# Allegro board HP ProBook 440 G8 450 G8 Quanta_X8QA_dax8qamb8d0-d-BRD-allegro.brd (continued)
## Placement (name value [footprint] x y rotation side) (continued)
C7735  0.1U/25V_4  [C0402]  136.75 18.39 270 top
C7736  3p/50V_2  [C0201]  121 68.5 0 top
C7737  0.1U/16V_4  [C0402]  95.45 79.86 225 top
C7738  12P/50V_4  [C0402]  110.36 101.72 270 top
C7739  100P/50V_4  [C0402]  111.33 101.72 90 top
C7740  2.2u/25V_4  [C0402_2]  113.03 102.84 270 top
C7741  0.1U/16V_4  [C0402]  114.12 102.84 90 top
C7742  2.2p/50V_4  [C0402]  109.4 101.72 90 top
C7743  2.2p/50V_4  [C0402]  124.48 96.47 270 top
C7744  12P/50V_4  [C0402]  118.74 99.24 0 top
C7745  100P/50V_4  [C0402]  127.07 100.94 90 top
C7746  2.2u/25V_4  [C0402_2]  125.98 100.94 270 top
C7747  0.1U/16V_4  [C0402]  89.05 78.41 225 top
C7748  100P/50V_4  [C0402]  36.4 52.6 0 top
C7749  2.2u/25V_4  [C0402_2]  34.92 54.81 225 top
C7750  0.1U/25V_4  [C0402]  35.68 54.05 45 top
C7751  0.1U/25V_4  [C0402]  64.03 14.7 90 bottom
C7752  0.1U/25V_4  [C0402]  107.06 111.86 180 top
C7753  68P/50V_4  [C0402]  107.06 110.89 180 top
C7754  0.1U/25V_4  [C0402]  153.57 102.66 225 top
C7755  68P/50V_4  [C0402]  155.65 100.73 225 top
C7756  0.1U/25V_4  [C0402]  179.37 89.71 0 top
C7757  2.2p/50V_4  [C0402]  106.95 71.61 270 top
C7758  0.1U/25V_4  [C0402]  111.58 72.41 270 top
C7759  100P/50V_4  [C0402]  107.93 71.61 270 top
C7760  3p/50V_2  [C0201]  134.64 81.46 180 top
C7761  100P/50V_4  [C0402]  129.23 77.82 180 top
C7762  3p/50V_2  [C0201]  113.74 89.86 315 top
C7763  3p/50V_2  [C0201]  129.51 100.99 270 bottom
C7764  100P/50V_4  [C0402]  130.38 100.73 90 bottom
C7765  2.2u/25V_4  [C0402_2]  36.24 27.35 0 top
C7766  0.1U/25V_4  [C0402]  39.9 27.68 0 top
C7767  2.2u/25V_4  [C0402_2]  112.44 96.75 180 bottom
C7768  2.2u/25V_4  [C0402_2]  152.73 19.43 180 top
CON1900  Current monitor conn.  [WTB-50450-0107C-001-10P-L-SMT]  151.33 107.01 0 bottom
CON3400  GS12401-1011-9H  [51693-0400T-V01-40P-L]  22.69 35.5 90 bottom
CON3401  *50376-00601-V01  [50376-00601-V01-6P-L]  8.61 27.76 90 bottom
CON3501  PDMR004019P1-1  [HDMI-PDMR004019P1-1-19P]  214 52.3 270 bottom
CON3601  51378-0040N-V01  [WTB-51378-0040N-V01-4P-L]  138.84 105.6 0 bottom
CON3700  2SJ3095-239251F  [AUDIO-2SJ3095-239251F-6P]  213.52 35.31 270 bottom
CON4100  LOTES_APCI0019-P00*A  [NGFF-NFSE0-S6710-TPH4-KE-SMT]  181.84 77.09 0 bottom
CON4202  NFSB0-S6710-TP20  [NGFF-NFSB0-S6710-TP20-KB-SMT]  193.16 3.74 180 bottom
CON4203  51273-00401-V01  [51273-00401-V01-4P-L]  196.44 48.45 0 bottom
CON4204  5-501709002000-6  [SIMCARD-5-501709002000-6-6P]  167.55 63.46 270 bottom
CON4300  SSD_NGFF_CONN_75P  [NGFF-NFSM0-S6710-TPH4-75P-KM]  8.09 11.5 90 bottom
CON4400  52509-00801-V01  [FPC-52509-00801-V01-8P-L]  28.84 3.75 180 bottom
CON4402  51536-01541-001  [51536-01541-V01-15P-L]  148.49 6.4 180 bottom
CON4700  50271-00201-001  [50271-00201-001-2P-L]  174.34 4.4 180 bottom
CON5000  51697-0420M-001  [FPC-51697-0420M-001-42P-L]  121.39 5.83 180 bottom
CON5002  51614-00801-V01  [51614-00801-V01-8P-L]  46.84 3.35 180 bottom
CON5200  52509-00801-V01  [FPC-52509-00801-V01-8P-L]  158.04 5.6 180 bottom
CON5202  52509-00801-V01  [FPC-52509-00801-V01-8P-L]  37.94 3.77 180 bottom
CON5400  51378-0040N-V01  [WTB-51378-0040N-V01-4P-L]  25.2 63.43 152.7 bottom
CON6201  TCRB5-9U6391  [UB3-TCRB5-9U6391-9P]  213.12 91.9 270 bottom
CON6202  TCRB5-9U6391  [UB3-TCRB5-9U6391-9P]  213.12 72.4 270 bottom
CON6300  UT12123-1090H-7H  [UB31-UT12123-1090H-7H-24P]  214.56 108.72 90 top
CON7600  158-1000902638  [SDCARD-158-1000902616-9P]  213.79 19.4 90 top
CON7602  52526-04001-001  [FPC-52526-04001-001-40P-L]  7.32 16.93 270 top
CON7603  52509-00601-V01  [FPC-52509-00601-V01-6P-L]  0.72 12.3 90 bottom
CON7700  *APS CONN.  [88511-180N-18P-L]  14.3 38.94 90 bottom
CON7701  TBT Debug conn.  [FPC-50506-0150B-V01-15P-L]  163.93 79.58 90 bottom
CON7702  EC debug conn.  [LVDS-50406-03001-V09-30P-R]  212.93 17.47 270 bottom
CON7703  *Samtec BSH-030-01  [BSH-030-01-L-D-A-TR-60P-RUV]  44.5 46.73 270 top
CON7704  52509-00801-V01  [FPC-52509-00801-V01-8P-L]  138.87 5.92 180 bottom
D1400  BAT54CW  [SOT23-1_7-65-3P]  159.05 69.82 90 top
D1500  RB500V-40  [D-1_85X1_25-2P-0_95H]  156.16 78.81 270 bottom
D1600  RB500V-40  [D-1_85X1_25-2P-0_95H]  152.35 67.03 90 bottom
D3300  *RB500V-40  [D-1_85X1_25-2P-0_95H]  19.91 44.12 90 top
D3500  BAT54AW-L  [SOT23-1_7-65-3P]  200.9 48.42 90 top
D3600  *MEK500V-40  [D-1_85X1_25-2P-0_95H]  187.4 45.9 90 top
D3700  Clamp-Diode  [C0402]  204.49 42.75 90 top
D3701  Clamp-Diode  [C0402]  201.8 31.82 90 top
D3702  Clamp-Diode  [C0402]  212.79 28.7 180 bottom
D3703  Clamp-Diode  [C0402]  204.77 42.74 270 bottom
D4200  RB500V-40  [D-1_85X1_25-2P-0_95H]  207.11 10.61 0 bottom
D4201  MEK500V-40  [D-1_85X1_25-2P-0_95H]  205.28 9.42 0 top
D4203  *Clamp-Diode  [C0402]  214.75 10.64 90 top
D4204  *Clamp-Diode  [C0402]  206.27 5.33 0 top
D4205  *Clamp-Diode  [C0402]  197.33 4.01 180 top
D4206  *Clamp-Diode  [C0402]  206.09 23.82 270 bottom
D5000  BAW56DW  [SOT363-2_1-65-6P]  140.9 10.85 0 bottom
D5001  BAW56DW  [SOT363-2_1-65-6P]  138.06 8.04 90 top
D5002  BAW56DW  [SOT363-2_1-65-6P]  140.7 7.85 270 top
D5003  BAW56DW  [SOT363-2_1-65-6P]  137.21 11.94 180 bottom
D5900  PESD5V0F1BSF  [D-0_6X0_3-0_32H-SMT]  206.07 105.18 270 top
D5901  PESD5V0F1BSF  [D-0_6X0_3-0_32H-SMT]  206.07 106.5 90 top
D5902  PESD5V0F1BSF  [D-0_6X0_3-0_32H-SMT]  206.07 102.44 270 top
D5903  PESD5V0F1BSF  [D-0_6X0_3-0_32H-SMT]  206.07 103.83 90 top
D5904  PESD5V0F1BSF  [D-0_6X0_3-0_32H-SMT]  206.98 112.8 90 top
D5905  PESD5V0F1BSF  [D-0_6X0_3-0_32H-SMT]  206.96 111.45 270 top
D5906  PESD5V0F1BSF  [D-0_6X0_3-0_32H-SMT]  206.56 110.11 90 top
D5907  PESD5V0F1BSF  [D-0_6X0_3-0_32H-SMT]  206.55 108.75 270 top
D6300  P4SMAFJ20A  [D-3_8X2_5]  205.31 103.32 0 bottom
D6306  PJE24VM5FN2  [D-1X0_6-0_53H]  208.49 106.16 180 bottom
D6307  PJE24VM5FN2  [D-1X0_6-0_53H]  208.99 112.19 180 bottom
D6309  PJE24VM5FN2  [D-1X0_6-0_53H]  211.2 110.08 90 bottom
D6310  PJE24VM5FN2  [D-1X0_6-0_53H]  209.19 106.47 270 top
D6313  SYT43L05SMD  [ESD3-0_985X0_585]  207.74 109.73 270 bottom
D6314  SYT43L05SMD  [ESD3-0_985X0_585]  206.4 108.94 270 bottom
D6900  MEK500V-40  [D-1_85X1_25-2P-0_95H]  81.99 96.44 180 bottom
D6901  BAT54SW-L  [SOT23-1_7-65-3P]  83.72 83 0 bottom
D6902  MEK500V-40  [D-1_85X1_25-2P-0_95H]  76.56 98.63 180 top
D7501  BAT54CW  [SOT23-1_7-65-3P]  21.74 31.21 270 top
EC1  22u/25V_8  [C0805]  62.53 15.54 270 bottom
EC2  22u/25V_8  [C0805]  94 17.47 0 bottom
EC3  22u/25V_8  [C0805]  45.67 16.84 90 bottom
EC4  1N/50V_4  [C0402]  162.99 101.42 0 top
EC5  22u/25V_8  [C0805]  47.65 16.84 90 bottom
EC2800  2200P/50V_4  [C0402]  184.12 21.27 180 top
EC2802  2.2U/10V_4  [C0402]  109.07 24.33 270 top
EC2803  82P/50V_4  [C0402]  184.12 20.2 180 top
EC2900  82P/50V_4  [C0402]  104.82 22.25 0 top
EC2901  2.2U/10V_4  [C0402]  101.29 26.24 270 top
EC2902  2200P/50V_4  [C0402]  104.85 23.21 0 top
EC2903  82P/50V_4  [C0402]  49.4 24.48 135 top
EC3600  *33P/50V_4  [C0402]  188.77 37.28 90 top
EC3601  *10P/50V_4  [C0402]  190.17 35.94 0 top
EC3602  0.1U/16V_4  [C0402]  194.05 36.01 270 bottom
EC3603  0.1U/16V_4  [C0402]  205.15 28.47 90 top
EC3604  *10P/50V_4  [C0402]  190.07 39.85 180 top
EC3605  *0.1U/16V_4  [C0402]  200.51 31.82 90 top
EC3606  *0.1U/16V_4  [C0402]  203.5 42.75 270 top
EC3607  *0.1U/16V_4  [C0402]  200.83 43.38 270 top
EC3700  *0.1U/16V_4  [C0402]  209.42 27.99 90 bottom
EC3701  *0.1U/16V_4  [C0402]  206.53 28 90 bottom
EC3702  *0.1U/16V_4  [C0402]  203.53 42.75 270 bottom
EC3703  0.1U/16V_4  [C0402]  211.91 42.87 270 top
EC3704  *0.1U/16V_4  [C0402]  201.95 43.38 270 top
EC4301  10U/6.3V_4  [C0402_2]  14.54 7.9 90 top
F3400  FUSE1A6V_POLY  [F2_1X1_4-2_2-0_8H]  27.25 46.78 180 top
F3401  FUSE SMD 1.1A 6V POLY  [F2_1X1_35-2_2-0_75H]  16.33 25.75 180 top
F3402  FUSE SMD 1.5A 24V POLY  [F4_5X3_2-5_23]  32.46 51.53 90 bottom
F3403  *FUSE SMD 1.5A 24V POLY  [F4_5X3_2-5_23]  14.37 35.41 0 top
F3405  *FUSE SMD 1.5A 24V POLY  [F4_5X3_2-5_23]  14.37 30.38 0 top
F3500  SPR-P110/1.1A/6V_0805  [F2_1X1_35-2_2-0_75H]  197.18 47.93 0 top
F4200  FUSE1A6V_POLY  [F2_1X1_4-2_2-0_8H]  202.28 48.31 90 bottom
F4400  SPR-P110/1.1A/6V_0805  [F2_1X1_35-2_2-0_75H]  32.33 8.23 180 bottom
F4401  FUSE SMD 1.1A 6V POLY  [F2_1X1_35-2_2-0_75H]  150.85 10.37 0 bottom
F5002  SPR-P110/1.1A/6V_0805  [F2_1X1_35-2_2-0_75H]  134.19 14.48 270 bottom
F5003  SPR-P110/1.1A/6V_0805  [F2_1X1_35-2_2-0_75H]  49.35 9.27 270 bottom
F5202  SPR-P110/1.1A/6V_0805  [F2_1X1_35-2_2-0_75H]  151 9.85 270 top
F5203  FUSE SMD 1.1A 6V POLY  [F2_1X1_35-2_2-0_75H]  39.52 10.13 180 bottom
F7603  FUSE SMD 1.1A 6V POLY  [F2_1X1_35-2_2-0_75H]  12.87 12.66 0 top
F7605  FUSE SMD 1.1A 6V POLY  [F2_1X1_35-2_2-0_75H]  12.88 10.53 0 top
F7606  FUSE SMD 1.1A 6V POLY  [F2_1X1_35-2_2-0_75H]  12.95 22.71 90 top
H7900  *H-600TGL-4  [H-600TGL-4]  213.74 0.75 0 top
H7901  *SPAD-X8Q-X8Q-5  [SPAD-X8Q-X8Q-5]  166.57 5.5 0 top
H7902  *SPAD-X8Q-X8Q-4  [SPAD-X8Q-X8Q-4]  101.37 5.53 0 top
H7903  *SPAD-X8Q-X8Q-4  [SPAD-X8Q-X8Q-4]  18.67 5.53 0 top
H7904  -  [H-TC197IBC126D126P2]  181.84 105.34 180 bottom
H7905  *H-TC276IC134BS1D134P2  [H-TC276IC134BS1D134P2]  23.22 73.45 0 top
H7906  *H-TC276IC134BC276D134P2  [H-TC276IC134BC276D134P2]  45.24 105.25 0 top
H7907  *H-TBC276IC154D154P2  [H-TBC276IC154D154P2]  194.24 63.07 0 top
H7908  *H-TC276IC150BC150D150PT  [H-TC276IC150BC150D150PT]  92.84 88.8 0 top
H7909  *H-TC276IC150BC150D150PT  [H-TC276IC150BC150D150PT]  92.84 60.2 0 top
H7910  *H-TC276IC150BC150D150PT  [H-TC276IC150BC150D150PT]  152.84 88.8 0 top
H7911  *H-TC276IC150BC150D150PT  [H-TC276IC150BC150D150PT]  152.84 60.2 0 top
H7912  *H-TC276IC150BC150D150PT  [H-TC276IC150BC150D150PT]  52.46 62.42 0 top
H7913  *H-TC276IC150BC150D150PT  [H-TC276IC150BC150D150PT]  83.22 92.18 0 top
H7914  *H-O98X59D98X59N  [H-O98X59D98X59N]  28.24 107.25 0 top
H7915  *H-600TGL-1  [H-600TGL-1]  209.44 118.25 0 top
H7916  *H-TC276IC134BC276D134P2  [H-TC276IC134BC276D134P2]  111.34 50.25 0 top
H7918  *2D-BARCODE-8X8-S  [2D-BARCODE-8X8-S]  96.59 43.25 180 bottom
H7919  *H-O80X100D80X100N  [H-O80X100D80X100N]  213.74 5.6 0 top
H7920  *H-C71D71N  [H-C71D71N]  205.04 114.55 0 top
H7921  *SPAD-RE138X98  [SPAD-RE138X98]  31.59 106.3 180 bottom
H7922  *SPAD-X8Q-X8Q-1  [SPAD-X8Q-X8Q-1]  18.67 5.85 180 bottom
H7923  *SPAD-X8Q-X8Q-2  [SPAD-X8Q-X8Q-2]  101.37 6.34 180 bottom
H7924  *SPAD-X8Q-X8Q-3  [SPAD-X8Q-X8Q-3]  166.57 6.35 180 bottom
JDIM2800  DDR4-DIMM0_H=4_RVS  [DDR4-D4AR0-26010-1P40-RVS-SMT]  149.8 24.31 180 bottom
JDIM2900  DDR3-DIMM0_H=5.2_RVS  [DDR4-D4AR0-26010-1P40-RVS-SMT]  72.84 24.31 180 bottom
L3400  *0.01_1%_6/S  [S0603]  27.96 36.19 90 top
L3401  120/300MA_S0_4  [R0402]  28.73 29.77 90 top
L3402  120/300MA_S0_4  [R0402]  29.77 25.8 270 top
L3403  BLM03AG121SN1D  [FILTER-BLM03EB500SN1D-2P]  32.36 30.83 0 bottom
L3600  *0_6/S  [S0603]  199.64 43.46 90 top
L3601  *Short_1206  [S1206]  192.61 44.3 270 top
L4700  *HCB1608KF-181T15/S  [S0603]  199.39 11.99 180 bottom
L5900  0.68uH_2.5x2.0x1.2  [L2_5X2-1_2H]  180.02 100.44 180 bottom
L5901  *0.01_1%_4/S  [S0402]  176.88 105.23 180 top
L6200  MCM2012B900GBE  [FILTER-MCM2012B900GBE-4P-SMT]  200.41 88.45 270 bottom
L6201  MCM2012B900GBE  [FILTER-MCM2012B900GBE-4P-SMT]  199.66 67.61 270 bottom
L6600  HCB1005KF-330T30  [R0402]  63.88 93.52 90 bottom
L6700  *HCB1608KF(300,2A)  [R0603]  61.47 62.96 180 bottom
L6701  HCB1005KF-330T30  [R0402]  63.29 62.81 270 bottom
LED7600  LED 3P WHITE/AMBER  [LEDLTW-326DSKF-5A-3P-SMT]  215.19 117.85 270 top
NOREF  -  [unnamed]  182.57 29.27 0 top
NOREF#2  -  [#2]  162.38 31.87 0 top
NOREF#3  -  [#2]  167.46 -31.93 0 top
NOREF#4  -  [unnamed]  119.5 92.89 0 top
NOREF#5  -  [#2]  4.78 -42.99 0 top
NOREF#6  -  [unnamed]  175.99 5.95 90 top
NOREF#7  -  [unnamed]  177.07 52.67 0 top
NOREF#8  -  [unnamed]  143.93 5.82 270 top
NOREF#9  -  [unnamed]  189.01 104.02 180 top
NOREF#10  -  [unnamed]  145.66 11.44 180 top
NOREF#11  -  [unnamed]  13.82 16.15 270 top
NOREF#12  -  [unnamed]  168.24 98.46 270 top
NOREF#13  -  [unnamed]  192.67 55.09 90 top
NOREF#14  -  [unnamed]  192.51 56.7 0 top
NOREF#15  -  [unnamed]  73.52 9.62 180 top
NOREF#16  -  [unnamed]  174.9 9.47 180 top
NOREF#17  -  [unnamed]  119.5 91.4 0 top
NOREF#18  -  [unnamed]  3.76 5.41 180 top
NOREF#19  -  [#2]  135.71 94.73 180 bottom
NOREF#20  -  [unnamed]  196.16 101.88 0 bottom
NOREF#21  -  [unnamed]  31.34 99.01 0 bottom
NOREF#22  -  [unnamed]  8.84 33.04 0 bottom
PC8000  0.1U/25V_4  [C0402]  154 102 90 bottom
PC8001  0.1U/25V_4  [C0402]  147.55 97.38 90 top
PC8002  1u/25V_4  [C0402]  151.95 99.56 180 top
PC8003  *1u/25V_4  [C0402]  183.23 88.59 180 top
PC8004  1u/25V_4  [C0402]  180.54 88.39 0 bottom
PC8005  2.2u/25V_4  [C0402_2]  154.38 100.4 0 bottom
PC8006  *1u/25V_4  [C0402]  181.46 88.47 0 top
PC8100  1N/50V_4  [C0402]  42.12 12.4 180 bottom
PC8101  3300p/50V_4  [C0402]  35.79 10.11 180 bottom
PC8102  0.22U/10V_4  [C0402]  37.13 10.31 90 bottom
PC8103  0.1U/16V_4  [C0402]  38.16 12.4 180 bottom
PC8104  *0.01U/50V_4  [C0402]  40.32 12.4 180 bottom
PC8105  0.1u/6.3V_2  [C0201]  190.55 12.75 0 bottom
PC8106  *1000P/50V_4  [C0402]  173.07 18.36 90 top
PC8107  *1000P/50V_4  [C0402]  182.88 11.38 90 bottom
PC8108  0.1U/16V_4  [C0402]  16.38 45.79 180 top
PC8109  1U/6.3V_4  [C0402]  186.74 12.32 270 bottom
PC8200  *1u/25V_6  [C0603]  175.69 87.63 270 bottom
PC8201  0.1U/25V_4  [C0402]  176.12 84.27 270 bottom
PC8202  *33u/25V_7343H2.9  [CC7343]  53.41 16.03 180 bottom
PC8203  0.1U/25V_4  [C0402]  59.66 12.9 180 top
PC8204  0.1U/25V_4  [C0402]  60.04 11.88 180 top
PC8205  0.1U/25V_4  [C0402]  61.44 12.9 180 top
PC8206  10u/25V_6  [C0603]  60.54 14.65 270 bottom
PC8207  *10u/25V_6  [C0603]  59.11 14.64 270 bottom
PC8208  2200P/50V_4  [C0402]  60.63 10.72 90 bottom
PC8209  0.1U/25V_4  [C0402]  59.61 10.72 270 bottom
PC8210  2.2u/16V_6  [C0603]  61.11 3.48 0 top
PC8211  1u/25V_6  [C0603]  62.38 9.55 180 top
PC8212  0.047U/25V_4  [C0402]  64.31 6.5 270 top
PC8213  *1000p/50V_4  [C0402]  56.77 8.91 90 bottom
PC8214  10u/25V_6  [C0603]  81.95 16.59 270 top
PC8215  10u/25V_6  [C0603]  80.52 16.59 270 top
PC8216  10u/25V_6  [C0603]  79.09 16.6 270 top
PC8217  0.1U/25V_4  [C0402]  75.08 12.06 90 bottom
PC8218  *68u/25V_7343H2.9  [CC7343]  69.8 15.21 180 top
PC8219  *2200p/50V_4  [C0402]  66.29 4.49 180 top
PC8220  0.1U/25V_4  [C0402]  67.77 9.22 0 top
PC8221  0.1U/25V_4  [C0402]  69.67 9.22 180 top
PC8222  0.1U/25V_4  [C0402]  71.58 9.22 180 top
PC8223  100P/50V_4  [C0402]  55.34 10.11 270 top
PC8224  100P/50V_4  [C0402]  54.23 10.08 270 top
PC8225  0.1U/16V_4  [C0402]  64.84 3.63 270 bottom
PC8226  *100p/50V_4  [C0402]  53.24 9.98 90 top
PC8227  220p/50V_4  [C0402]  52.5 6.09 180 top
PC8400  3900p/50V_4  [C0402]  190.5 54.53 180 bottom
PC8401  0.22u/10V_4  [C0402]  174.7 83.39 0 top
PC8402  100p/50V_4  [C0402]  174.83 84.91 270 top
PC8403  100p/50V_4  [C0402]  54.56 3.51 0 top
PC8404  *1u/6.3V_4  [C0402]  58.11 8.81 180 bottom
PC8405  2200p/25V_2  [C0201]  76.76 17.42 270 top
PC8406  0.1U/25V_4  [C0402]  76.07 12.06 90 bottom
PC8407  0.1U/25V_4  [C0402]  80.19 15.79 270 bottom
PC8408  *220p/50V_4  [C0402]  48 9.64 180 top
PC8409  100p/50V_4  [C0402]  82.21 15.8 90 bottom
PC8410  100p/50V_4  [C0402]  83.17 15.8 90 bottom
PC8411  *100p/50V_4  [C0402]  87.43 16.41 0 bottom
PC8600  10u/25V_6  [C0603]  139.31 15.38 270 bottom
PC8601  10u/25V_6  [C0603]  137.89 15.38 270 bottom
PC8602  *2.2u/25V_4  [C0402_2]  136.09 14.93 180 bottom
PC8603  *2.2u/25V_4  [C0402_2]  136.09 13.75 180 bottom
PC8604  *2.2u/25V_4  [C0402_2]  137.41 14.27 90 top
PC8605  2.2U/10V_4  [C0402]  144.4 17.52 270 bottom
PC8606  0.1U/25V_4  [C0402]  137.31 11.91 270 top
PC8607  0.1U/25V_4  [C0402]  139.27 17.39 0 bottom
PC8608  2200P/50V_4  [C0402]  138.49 14.27 90 top
PC8609  0.1U/25V_4  [C0402]  145.49 11.9 270 bottom
PC8610  *2200p/50V_4  [C0402]  144.88 13.59 0 top
PC8611  22U/6.3V_6  [C0603]  146.87 16.04 270 top
PC8612  22U/6.3V_6  [C0603]  148.27 13.39 90 top
PC8613  22U/6.3V_6  [C0603]  148.29 16.04 270 top
PC8614  *22U/6.3V_6  [C0603]  146.86 13.39 90 top
PC8615  0.1u/6.3V_2  [C0201]  149.45 16.08 90 top
PC8616  *0.1u/6.3V_2  [C0201]  140.41 12.85 90 bottom
PC8617  1U/6.3V_4  [C0402]  142.41 12.74 0 bottom
PC8618  2.2U/10V_4  [C0402]  165.4 8.94 90 bottom
PC8619  10u/25V_6  [C0603]  164.79 16.94 0 bottom
PC8620  2.2u/25V_4  [C0402_2]  166.09 14.3 270 top
PC8621  *2.2u/25V_4  [C0402_2]  167.28 14.3 270 top
PC8622  *2.2u/25V_4  [C0402_2]  164.89 14.3 270 top
PC8623  2.2u/25V_4  [C0402_2]  168.48 14.3 270 top
PC8624  2200P/50V_4  [C0402]  169.57 14.3 270 top
PC8625  0.1U/25V_4  [C0402]  169.92 15.77 0 top
PC8626  0.1U/25V_4  [C0402]  168.53 20.34 90 top
PC8627  10u/6.3V_4  [C0402_2]  166.47 8.94 270 bottom
PC8628  0.1U/25V_4  [C0402]  169.62 17.4 180 bottom
PC8629  *2200p/50V_4  [C0402]  174.45 16.48 180 top
PC8630  22U/6.3V_6  [C0603]  171.49 7.41 0 bottom
PC8631  22U/6.3V_6  [C0603]  174.7 13.51 270 top
PC8632  22U/6.3V_6  [C0603]  171.85 13.51 270 top
PC8633  22U/6.3V_6  [C0603]  171.47 8.99 0 bottom
PC8634  0.1u/6.3V_2  [C0201]  175.77 13.54 270 top
PC8635  1000p/25V_4  [C0402]  170.86 10.46 90 top
PC8636  *0.1u/6.3V_2  [C0201]  168.5 9.95 270 bottom
PC8637  *15u/25V_3528H1.1  [C3528]  163.32 11.88 90 bottom
PC8638  100u/6.3V_3528H1.9  [C3528]  179.86 12.24 270 bottom
PC8700  1u/6.3V_2  [C0201]  107.54 11 0 bottom
PC8701  *2.2u/25V_4  [C0402_2]  93.93 15.67 0 bottom
PC8702  *2.2u/25V_4  [C0402_2]  93.65 15.66 0 top
PC8703  2200p/50V_4  [C0402]  98.26 9.85 90 bottom
PC8704  0.1U/25V_4  [C0402]  92.96 17.5 90 top
PC8705  10u/6.3V_4  [C0402_2]  102.44 8.86 90 top
PC8706  *0.1u/6.3V_2  [C0201]  107.57 10.6 180 top
PC8707  10u/25V_6  [C0603]  97.07 9.41 90 bottom
PC8708  *2.2u/25V_4  [C0402_2]  95.73 17.98 180 top
PC8709  0.1U/25V_4  [C0402]  99.22 9.85 90 bottom
PC8710  0.1U/25V_4  [C0402]  100.43 13.33 180 top
PC8711  0.1u/6.3V_2  [C0201]  106.63 6.8 180 top
PC8712  0.033u/25V_4  [C0402]  104.68 8 90 top
PC8713  *10u/6.3V_4  [C0402_2]  100.82 10.83 0 top
PC8714  1u/6.3V_4  [C0402]  104.65 15.19 180 top
PC8715  22u/6.3V_6  [C0603]  112.42 13.82 180 bottom
PC8716  22u/6.3V_6  [C0603]  105.56 9.04 180 bottom
PC8717  22u/6.3V_6  [C0603]  112.42 12.39 180 bottom
PC8718  22u/6.3V_6  [C0603]  112.42 15.24 180 bottom
PC8719  0.1u/6.3V_2  [C0201]  110.41 18.01 90 bottom
PC8720  *2200p/25V_2  [C0201]  99.8 15.75 270 top
PC8721  4.7u/6.3V_4  [C0402_2]  185.14 13.79 180 bottom
PC8722  22U/6.3V_6  [C0603]  187.78 16.05 180 bottom
PC8723  *22U/6.3V_6  [C0603]  187.78 14.5 180 bottom
PC8724  0.1u/6.3V_2  [C0201]  186.99 18.11 0 bottom
PC8725  *22p/50V_4  [C0402]  188.41 17.63 270 bottom
PC8726  0.22u/6.3V_2  [C0201]  173.58 49.98 90 top
PC8800  0.1u/16V_4  [C0402]  79.83 110.92 180 top
PC8801  0.22u/25V_6  [C0603]  84.15 110.84 0 bottom
PC8802  1u/6.3V_4  [C0402]  81.86 108.48 270 top
PC8803  0.1U/25V_4  [C0402]  89.16 102.87 270 bottom
PC8804  0.047u/16V_4  [C0402]  89.76 104.7 180 top
PC8805  33p/50V_4  [C0402]  83.42 102.59 270 top
PC8806  0.01u/50V_4  [C0402]  82.47 100.86 270 top
PC8807  2200P/50V_4  [C0402]  87.27 101.29 90 top
PC8808  0.01u/50V_4  [C0402]  91.49 104.7 180 top
PC8809  0.022u/25V_4  [C0402]  89.84 106.9 180 top
PC8810  0.022u/25V_4  [C0402]  89.84 107.88 180 top
PC8811  *0.1u/6.3V_2  [C0201]  83.08 106.53 180 bottom
PC8812  *4.7u/6.3V_4  [C0402_2]  83.82 101.12 180 top
PC8813  820p/50V_4  [C0402]  85.89 101.19 0 top
PC8814  330p/50V_4  [C0402]  86.27 98.63 270 top
PC8815  *4.7u/6.3V_4  [C0402_2]  85.89 100.1 0 top
PC8816  330p/50V_4  [C0402]  88.26 99.57 90 top
PC8817  *0.1u/6.3V_2  [C0201]  81.38 103.17 0 top
PC8818  330p/50V_4  [C0402]  84.77 103.08 270 bottom
PC8819  4700p/25V_4  [C0402]  83.34 105.28 90 bottom
PC8900  10u/25V_6  [C0603]  97.34 110.45 270 bottom
PC8901  2200P/50V_4  [C0402]  98.4 111.5 90 top
PC8902  10u/25V_6  [C0603]  97.33 106.43 90 bottom
PC8903  2.2u/25V_4  [C0402_2]  101.88 111.5 270 top
PC8904  2.2u/25V_4  [C0402_2]  99.49 111.5 270 top
PC8905  2.2u/25V_4  [C0402_2]  100.68 111.5 270 top
PC8906  0.1U/25V_4  [C0402]  101.29 105.36 90 top
PC8907  0.1U/25V_4  [C0402]  27.76 85.54 90 top
PC8908  2.2u/6.3V_4  [C0402]  93.69 109.44 0 bottom
PC8909  0.22u/25V_6  [C0603]  95.93 111.26 90 bottom
PC8910  2.2u/6.3V_4  [C0402]  90.34 107.37 180 bottom
PC8917  *330u/2.5V_7343H1.9  [CC7343]  104.51 93.51 180 bottom
PC8918  330u/2.5V_7343H1.9  [CC7343]  114.01 93.51 0 bottom
PC8919  *2200p/50V_4  [C0402]  94.55 103.96 180 top
PC8920  10u/25V_6  [C0603]  111.05 104.66 90 bottom
PC8921  2200P/50V_4  [C0402]  100 105.38 270 top
PC8922  10u/25V_6  [C0603]  109.6 104.66 90 bottom
PC8923  *2.2u/25V_4  [C0402_2]  103.07 111.5 270 top
PC8924  2.2u/25V_4  [C0402_2]  104.61 106.26 90 top
PC8925  2.2u/25V_4  [C0402_2]  105.79 106.25 90 top
PC8926  0.1U/25V_4  [C0402]  107.03 106.25 90 top
PC8927  0.22u/25V_6  [C0603]  107.24 111.67 90 bottom
PC8928  2.2u/6.3V_4  [C0402]  105.83 109.8 0 bottom
PC8929  2.2u/6.3V_4  [C0402]  103.33 106.85 270 bottom
PC8937  *220u/2.5V_3528H1.1  [C3528]  114.74 73.94 180 top
PC8938  *2200p/50V_4  [C0402]  104.16 103.83 270 top
PC8939  68u/25V_7343H2.9  [CC7343-3H]  100.45 107.76 270 bottom
PC9100  1u/6.3V_4  [C0402]  111.42 107.75 0 bottom
PC9101  2200P/50V_4  [C0402]  115.23 111.45 90 bottom
PC9102  0.1U/25V_4  [C0402]  114.16 111.45 270 bottom
PC9103  *2.2u/25V_4  [C0402_2]  121.74 108.76 90 top
PC9104  *2.2u/25V_4  [C0402_2]  123.06 108.76 90 top
PC9105  *2.2u/25V_4  [C0402_2]  120.55 108.76 90 top
PC9106  *2.2u/25V_4  [C0402_2]  119.35 108.76 90 top
PC9107  68u/25V_7343H2.9  [CC7343-3H]  123.85 108.65 0 bottom
PC9108  0.1U/25V_4  [C0402]  111.48 111.86 0 bottom
PC9109  0.22u/25V_6  [C0603]  113.59 103.83 180 bottom
PC9110  22U/6.3V_6  [C0603]  128.43 101.03 270 bottom
PC9111  22U/6.3V_6  [C0603]  127.01 101.03 270 bottom
PC9112  22U/6.3V_6  [C0603]  132.43 99.44 180 bottom
PC9113  22U/6.3V_6  [C0603]  124.66 100.99 270 top
PC9114  22U/6.3V_6  [C0603]  123.22 102.29 270 top
PC9118  *330u/2.5V_7343H1.9  [CC7343]  126.32 96.86 180 bottom
PC9119  0.22u/25V_6  [C0603]  116.22 103.83 0 bottom
PC9120  *2200p/50V_4  [C0402]  118.64 104.32 180 top
PC9121  *0.1u/6.3V_2  [C0201]  118.44 105.48 180 bottom
PC9122  10u/25V_6  [C0603]  117.14 110.03 180 bottom
PC9123  10u/25V_6  [C0603]  112.37 110.67 0 bottom
PC9201  10u/25V_6  [C0603]  120.06 17.17 270 bottom
PC9202  0.1U/25V_4  [C0402]  117.17 15.16 90 bottom
PC9203  0.1U/25V_4  [C0402]  116.76 16.9 90 bottom
PC9204  *10u/25V_6  [C0603]  117.04 12.95 90 bottom
PC9205  *2.2u/25V_4  [C0402_2]  118.46 13.08 90 bottom
PC9206  *2.2u/25V_4  [C0402_2]  114.88 15.17 270 bottom
PC9207  *2.2u/25V_4  [C0402_2]  116.08 15.17 270 bottom
PC9208  2200P/50V_4  [C0402]  115.24 13.44 270 bottom
PC9209  1u/10V_4  [C0402]  123.33 12.49 270 bottom
PC9210  0.1U/25V_4  [C0402]  126.11 12.8 180 bottom
PC9211  22U/6.3V_6  [C0603]  132.99 17.42 180 bottom
PC9212  22U/6.3V_6  [C0603]  130.99 12.93 90 bottom
PC9213  22U/6.3V_6  [C0603]  132.41 12.93 90 bottom
PC9214  *22U/6.3V_6  [C0603]  128.95 12.57 0 bottom
PC9215  *2200p/25V_2  [C0201]  128.24 12.85 90 top
PC9216  0.1U/16V_2  [C0201]  129.18 12.85 270 top
PC9217  1u/6.3V_2  [C0201]  121.56 12.3 0 bottom
PC9218  *220p/50V_2  [C0201]  121.92 13.08 180 top
PC9500  0.1U/16V_4  [C0402]  27.67 10.16 180 top
PC9501  0.1U/16V_4  [C0402]  22.93 11.13 270 top
PC9502  0.1U/16V_4  [C0402]  160.58 13.82 270 top
PC9503  0.1U/16V_4  [C0402]  154.13 12.36 90 top
PC9504  *10U/6.3V_6  [C0603]  21.74 11.55 270 top
PC9505  0.1U/16V_4  [C0402]  17.73 16.43 270 top
PC9506  *10U/6.3V_6  [C0603]  158.85 7.44 270 top
PC9507  0.1U/16V_4  [C0402]  157.58 7.55 270 top
PC9508  0.1U/16V_4  [C0402]  154.66 7.64 90 top
PC9509  0.1U/16V_4  [C0402]  25.98 14.3 270 top
PC9510  *10U/6.3V_6  [C0603]  27.56 11.96 90 top
PC9511  *10U/6.3V_6  [C0603]  153.9 10.19 270 top
PC9512  0.1U/16V_4  [C0402]  159.54 13.79 270 top
PC9513  0.1U/16V_4  [C0402]  25.05 7.8 90 top
PC9514  *0.1U/16V_4  [C0402]  23.36 8.57 0 top
PC9515  1N/50V_4  [C0402]  24.06 14.3 270 top
PC9516  1N/50V_4  [C0402]  25.02 14.3 270 top
PC9517  *0.1U/16V_4  [C0402]  26.02 7.8 90 top
PC9518  *0.1U/16V_4  [C0402]  158.14 14.22 180 top
PC9519  1N/50V_4  [C0402]  156.61 7.55 90 top
PC9520  1N/50V_4  [C0402]  155.65 7.55 90 top
PC9521  *0.1U/16V_4  [C0402]  156.72 15.34 180 top
PC9522  *0.1U/16V_4  [C0402]  178.92 66.83 180 top
PC9523  0.1U/16V_4  [C0402]  176.35 64.97 180 bottom
PC9526  *10U/6.3V_6  [C0603]  171.7 69.44 180 top
PC9527  0.1U/16V_4  [C0402]  178.56 69.34 180 top
PC9528  *10U/6.3V_6  [C0603]  178.94 70.71 180 top
PC9529  *0.1U/16V_4  [C0402]  172.18 73.56 90 top
PC9534  0.1U/16V_4  [C0402]  175.23 64.31 180 top
PC9536  *0.1U/16V_4  [C0402]  173.3 64.13 0 top
PC9537  *1N/50V_4  [C0402]  175.16 71.8 270 top
PC9538  1N/50V_4  [C0402]  176.22 71.8 270 top
PC9543  0.1U/16V_4  [C0402]  176.71 64.72 90 top
PC9601  0.1U/16V_4  [C0402]  145.73 97.15 180 bottom
PC9605  0.1U/16V_4  [C0402]  151.46 103.45 180 top
PC9800  1N/50V_4  [C0402]  33.22 99.79 270 top
PC9801  2.2u/10V_4  [C0402]  31.37 104.54 0 top
PC9802  0.047u/25V_4  [C0402]  36.02 106.98 90 top
PC9803  4.7U/6.3V_4  [C0402_2]  38.53 103.45 180 top
PC9804  0.01u/16V_2  [C0201]  32 103.43 90 top
PC9805  *0.1u/6.3V_2  [C0201]  33.6 101.01 90 bottom
PC9900  10u/25V_6  [C0603]  75.54 111.81 0 bottom
PC9901  10u/25V_6  [C0603]  78.2 111.81 180 bottom
PC9902  *10u/25V_6  [C0603]  72.79 111.76 180 bottom
PC9903  1u/25V_4  [C0402]  76.73 105.86 0 bottom
PC9904  2200P/50V_4  [C0402]  77.75 111.81 180 top
PC9906  1u/6.3V_4  [C0402]  79.78 108.1 90 bottom
PC9907  1u/25V_4  [C0402]  78.18 105 90 bottom
PC9909  330u/2.5V_3528H1.9  [C3528]  66.75 101.04 270 bottom
PC9910  *2200p/25V_2  [C0201]  72.74 104.65 180 bottom
PC9911  10u/25V_6  [C0603]  51.38 101.85 90 bottom
PC9912  10u/25V_6  [C0603]  51.23 105.08 270 bottom
PC9913  22u/25V_3528H1.9  [C3528]  67.33 108.3 90 bottom
PC9914  1u/6.3V_4  [C0402]  55.29 105.15 180 bottom
PC9915  *10u/25V_6  [C0603]  49.96 101.85 90 bottom
PC9916  1u/25V_4  [C0402]  57.05 103.38 270 bottom
PC9917  2200P/50V_4  [C0402]  71.83 110.36 180 top
PC9918  1u/25V_4  [C0402]  57.05 105.15 180 bottom
PC9920  330u/2.5V_3528H1.9  [C3528]  70.15 101.04 270 bottom
PC9921  *2200p/25V_2  [C0201]  57.22 97.56 270 bottom
PC9922  0.1U/25V_4  [C0402]  65.4 105.53 180 top
PC9923  22u/25V_3528H1.9  [C3528]  70.84 108.28 90 bottom
PC9924  15u/25V_7343H1.2  [CC7343]  54.73 101.67 180 top
PC9925  15u/25V_7343H1.2  [CC7343]  75.13 103.73 0 top
PC9926  *68u/25V_7343H2.9  [CC7343]  28.27 14.86 180 bottom
PC10200  10u/25V_6  [C0603]  32.54 88.31 90 bottom
PC10201  10u/25V_6  [C0603]  31.29 92.17 270 top
PC10202  *2.2u/25V_4  [C0402_2]  30.01 89 180 top
PC10203  *2.2u/25V_4  [C0402_2]  31.18 90.27 180 top
PC10204  *2.2u/25V_4  [C0402_2]  29.72 90.58 90 top
PC10206  2200p/25V_2  [C0201]  31.8 87.17 90 top
PC10207  4.7u/6.3V_4  [C0402_2]  25.69 89.51 180 bottom
PC10208  0.1U/25V_4  [C0402]  32.25 91.31 180 bottom
PC10209  0.1U/25V_4  [C0402]  28.09 87.78 270 top
PC10210  0.1U/25V_4  [C0402]  24.41 85.6 180 bottom
PC10211  22u/6.3V_6  [C0603]  27.86 83.28 90 top
PC10212  22u/6.3V_6  [C0603]  29.28 83.28 270 top
PC10213  22U/6.3V_6  [C0603]  25.02 83.28 270 top
PC10214  22U/6.3V_6  [C0603]  26.44 83.28 270 top
PC10215  0.1u/6.3V_2  [C0201]  23.95 83.31 90 top
PC10216  *2200p/25V_2  [C0201]  31.85 84.15 270 bottom
PC10217  *0.1u/6.3V_2  [C0201]  27.56 91.18 270 top
PC10218  2200p/50V_4  [C0402]  26.21 91.06 90 bottom
PC10219  22u/6.3V_6  [C0603]  27.13 78.41 270 top
PC10220  22u/6.3V_6  [C0603]  24.86 81.25 0 top
PC10221  *68u/25V_7343H2.9  [CC7343]  28.27 19.63 180 bottom
PC10500  4.7u/6.3V_4  [C0402_2]  69.39 60.83 270 bottom
PC10501  22U/6.3V_6  [C0603]  58.77 57.53 90 bottom
PC10502  *22U/6.3V_6  [C0603]  60.3 57.53 90 bottom
PC10503  *0.1u/6.3V_2  [C0201]  62.03 59.86 90 bottom
PC10504  *0.1u/6.3V_2  [C0201]  65.86 56.38 180 bottom
PC10505  *22p/50V_4  [C0402]  73.55 56.55 0 bottom
PC10506  0.1U/16V_4  [C0402]  89.23 70.3 90 top
PC10507  0.1U/16V_4  [C0402]  87.78 76.57 270 top
PC10508  *10U/6.3V_6  [C0603]  85.16 72.74 0 top
PC10509  0.1U/16V_4  [C0402]  86.66 71.09 90 top
PC10510  0.1U/16V_4  [C0402]  86.79 77.24 270 top
PC10511  *10U/6.3V_6  [C0603]  84.99 76.27 0 top
PC10512  0.1U/16V_4  [C0402]  91.31 73.86 180 top
PC10513  *0.1U/16V_4  [C0402]  91.31 74.88 180 top
PC10514  1N/50V_4  [C0402]  84.66 74.09 0 top
PC10515  1N/50V_4  [C0402]  84.66 75.08 0 top
PC10516  *0.1U/16V_4  [C0402]  91.34 72.49 180 top
PC10624  22U/6.3V_6  [C0603]  173.28 13.51 270 top
PC10625  22u/6.3V_6  [C0603]  133.35 91.84 0 top
PC10626  0.1u/6.3V_2  [C0201]  132.69 92.94 180 top
PC10627  0.1u/6.3V_2  [C0201]  133.37 97.03 180 top
PC10628  22u/6.3V_6  [C0603]  136.75 99.13 180 top
PC10629  *10u/6.3V_4  [C0402_2]  130.1 93.16 0 top
PC10630  0.1u/6.3V_2  [C0201]  130.43 94.13 180 top
PC10631  0.1u/6.3V_2  [C0201]  129.82 97.15 90 top
PC10632  *10u/6.3V_4  [C0402_2]  128.85 96.52 270 top
PC10633  0.1u/6.3V_2  [C0201]  135.05 95.98 180 top
PC10634  *0.1u/6.3V_2  [C0201]  134.48 97.64 270 top
PC10635  *0.1u/6.3V_2  [C0201]  135.05 95.24 0 top
PC10636  *10p/25V_2  [C0201]  130.43 94.89 0 top
PC10637  *10p/25V_2  [C0201]  130.43 95.65 180 top
PC10638  *0.1U/16V_4  [C0402]  17.48 42.74 90 top
PC10639  *0.1U/16V_4  [C0402]  20.72 50.77 270 top
PC10640  *0.1U/16V_4  [C0402]  123.98 104.49 90 top
PC10641  *0.1U/16V_4  [C0402]  17.88 39.22 0 top
PC10642  *0.1U/16V_4  [C0402]  123.87 106.83 270 top
PCN8000  50224-00701-001  [50224-00701-001-7P-L]  163.84 104.35 0 bottom
PCN8400  51362-0100T-V01  [WTB-51362-0100T-V01-10P-L]  86.74 8.32 180 bottom
PD8000  *P4SMAFJ20A  [D-3_8X2_5]  146.28 100.15 180 bottom
PD8001  PDZ5.1B  [D-SOD323-1_7X1_25-PMEG4005AEA]  174.32 90.29 90 bottom
PD8002  *RB500V-40  [D-1_85X1_25-2P-0_95H]  197.33 76.15 0 bottom
PD8100  BAT54AW-L  [SOT23-1_7-65-3P]  184.3 57.75 180 bottom
PD8200  *P4SMAFJ20A  [D-3_8X2_5]  54.28 12.11 180 bottom
PD8201  PDZ5.1B  [D-SOD323-1_7X1_25-PMEG4005AEA]  52.96 17.17 0 top
PD8202  BAS316  [D-1_7X1_25-2P]  63.88 14.77 90 top
PD8203  *UDZ8V2B-7  [D-SOD323-1_7X1_3-B0530WS]  64.01 3.33 0 top
PD8204  *BAS316  [D-1_7X1_25-2P]  66.7 11.2 0 top
PD8205  BAT54CW  [SOT23-1_7-65-3P]  171.93 104.39 180 bottom
PD8206  SX34  [D-4_3X2_7]  72.67 16.84 180 bottom
PD8207  BAS316  [D-1_7X1_25-2P]  53.79 9.6 180 bottom
PD8400  AZ5125-01H.R7G  [D-SOD523-1_2X0_8-0_65H]  81.23 17.37 0 bottom
PD8401  AZ5125-01H.R7G  [D-SOD523-1_2X0_8-0_65H]  87.96 17.79 180 bottom
PD8402  *PDZ5.6B  [D-SOD323-1_7X1_25-PMEG4005AEA]  85.55 16.68 90 bottom
PD8700  RB500V-40  [D-1_85X1_25-2P-0_95H]  171.65 48.46 90 top
PD9600  BAT54CW  [SOT23-1_7-65-3P]  141.98 92.58 0 top
PD9601  *BAT54CW  [SOT23-1_7-65-3P]  138.89 92.66 0 top
PD9602  *BAT54CW  [SOT23-1_7-65-3P]  144.68 100.56 180 top
PD9603  BAT54CW  [SOT23-1_7-65-3P]  141.6 98.07 0 top
PD9604  *BAT54CW  [SOT23-1_7-65-3P]  138.49 95.37 0 top
PD9800  *RB500V-40  [D-1_85X1_25-2P-0_95H]  36.93 104.49 90 bottom
PD9801  *RB500V-40  [D-1_85X1_25-2P-0_95H]  32.26 102.16 90 bottom
PD10500  *RB500V-40  [D-1_85X1_25-2P-0_95H]  90.75 77.26 270 top
PL8000  *Short_0805  [S0805]  150.54 100.65 90 bottom
PL8001  *Short_0805  [S0805]  152.52 100.65 90 bottom
PL8202  2.2uH_7x7x3  [L6_6X6_6-3H]  70.81 5.79 0 bottom
PL8400  *Short_1206  [S1206]  79.68 12.9 90 top
PL8600  HCB1608KF-121T30  [R0603]  136.17 16.84 270 bottom
PL8601  1.5uH_7x7x3  [L6_6X6_6-3H]  149.55 14.93 0 bottom
PL8602  HCB1608KF-121T30  [R0603]  167.23 18.11 270 top
PL8603  HCB1608KF-121T30  [R0603]  168.76 18.11 270 top
PL8604  1.5uH_7x7x3  [L6_6X6_6-3H]  174.04 14.55 0 bottom
PL8700  HCB1608KF-121T30  [R0603]  94.16 17.68 270 top
PL8701  1uH_7x7x3  [L6_6X6_6-2_8H]  106.5 14.96 0 bottom
PL8702  2.2uH_2.5x2.0x1.2  [L2_5X2-1_2]  184.88 16.74 90 bottom
PL8900  HCB1608KF-121T30  [R0603]  97.36 106.98 90 top
PL8901  HCB1608KF-121T30  [R0603]  98.78 106.98 90 top
PL8902  0.24uH_7x7x3  [L6_6X6_6-2_8H]  97.76 99.44 0 bottom
PL8903  0.24uH_7x7x3  [L6_6X6_6-2_8H]  107.14 99.49 180 bottom
PL8904  HCB1608KF-121T30  [R0603]  94.51 106.98 90 top
PL8905  HCB1608KF-121T30  [R0603]  95.93 106.98 90 top
PL9100  HCB1608KF-121T30  [R0603]  115.14 108.63 180 top
PL9101  0.22uH_7x7x3  [L6_6X6_6-2_8H]  116.89 99.51 0 bottom
PL9102  HCB1608KF-121T30  [R0603]  115.14 107.21 180 top
PL9200  1uH_5x5x3  [L4_5X4_7-2_8H]  127.76 15.9 0 bottom
PL9201  HCB1608KF-121T30  [R0603]  118.64 16.38 270 bottom
PL9900  0.15uH_7x7x3  [L6_6X6_6-2_8H]  75.46 100.38 270 bottom
PL9901  0.15uH_7x7x3  [L6_6X6_6-2_8H]  61.49 100.43 270 bottom
PL9902  *Short_0805  [S0805]  68.5 110.06 180 top
PL9903  *Short_0805  [S0805]  68.5 108.05 180 top
PL10200  HCB1608KF-121T30  [R0603]  30.01 87.58 0 top
PL10201  0.68uH_7x7x3  [L6_6X6_6-2_8H]  27.92 81.33 270 bottom
PL10500  1uH_2.5x2.0x1.2  [L2_5X2-1_2]  63.59 57.8 180 bottom
PQ8000  EMB03P03H  [POWER-5_2X5_55-1_27-5P]  149.52 95.19 90 bottom
PQ8001  AONR32320C  [POWER-3X3-65-5P-ADNR21357]  185.06 86 180 bottom
PQ8002  BSS84  [SOT23-2-95-3P]  148.59 100.05 180 top
PQ8003  PJA138K  [SOT23-2-95-3P]  197.56 73.26 180 bottom
PQ8004  PJA138K  [SOT23-2-95-3P]  139.9 98.17 270 bottom
PQ8006  AONR21357  [POWER-3X3-65-5P-ADNR21357]  180.95 85.88 180 bottom
PQ8007  AONR21357  [POWER-3X3-65-5P-ADNR21357]  172.92 86.87 0 bottom
PQ8008  PMBT3906  [SOT23-2-95-3P]  168.6 102.56 0 top
PQ8009  BSS84  [SOT23-2-95-3P]  174.83 98.88 0 bottom
PQ8010  BSS84  [SOT23-2-95-3P]  171.91 101.29 0 bottom
PQ8011  PMBT3906  [SOT23-2-95-3P]  159.43 104.7 90 top
PQ8012  MMDT2907AQ  [SOT363-2_1-65-6P-PJ4N3KDW]  176.65 90.73 180 bottom
PQ8013  MMDT2907AQ  [SOT363-2_1-65-6P-PJ4N3KDW]  173.33 83 0 bottom
PQ8200  AONS21357  [POWER-5_2X5_55-1_27-5P]  68.53 12.14 180 bottom
PQ8201  BSS84  [SOT23-2-95-3P]  57.07 15.34 180 top
PQ8202  MMDT2907AQ  [SOT363-2_1-65-6P-PJ4N3KDW]  53.21 15.01 180 top
PQ8203  AONR32320C  [POWER-3X3-65-5P-ADNR21357]  63.12 11.78 270 bottom
PQ8204  AONR32320C  [POWER-3X3-65-5P-ADNR21357]  64.64 7.62 180 bottom
PQ8205  2N7002K  [SOT23-2-95-3P]  53.82 5.28 90 bottom
PQ8400  PMBT3906  [SOT23-2-95-3P]  190.52 56.82 0 bottom
PQ8401  PMST3904  [SOT23-1_7-65-3P]  190.57 47.19 90 bottom
PQ8402  2N7002K  [SOT23-2-95-3P]  190.83 51.51 0 bottom
PQ8403  2N7002K  [SOT23-2-95-3P]  156.87 62.81 0 bottom
PQ8404  *PMBT3906  [SOT23-2-95-3P]  47.09 6.41 90 top
PQ8405  *PMBT3906  [SOT23-2-95-3P]  43.63 8.97 0 top
PQ8700  AONY36356  [POWER-5_2X5_55-1_27-7P-1H]  99.13 14.04 180 bottom
PQ8702  *2N7002K  [SOT23-2-95-3P]  108.82 8.47 0 top
PQ8703  2N7002KDW  [SOT363-2_1-65-6P]  162.34 15.46 90 top
PQ9100  2N7002KDW  [SOT363-2_1-65-6P]  126.25 103.93 180 bottom
PQ9601  *2N7002K  [SOT23-2-95-3P]  145.62 94.05 0 top
PQ9800  PJT7828  [SOT363-2_1-65-6P-PJT7828]  56.06 94.13 0 bottom
PQ9801  *BSS84  [SOT23-2-95-3P]  39.44 102 90 bottom
PQ9802  *PJE138K  [SOT23-1_38-5-3P]  36.14 100.94 180 bottom
PQ10200  *PJT7828  [SOT363-2_1-65-6P-PJT7828]  23.71 63.14 270 top
PQ10500  PJT7828  [SOT363-2_1-65-6P-PJT7828]  52.81 57.6 0 bottom
PQ10501  PJT7828  [SOT363-2_1-65-6P-PJT7828]  69.39 99.41 180 top
PQ10603  PJT7828  [SOT363-2_1-65-6P-PJT7828]  159.28 79.6 270 bottom
PR8000  220K_5%_2  [R0201]  151.9 97.93 0 top
PR8001  20K_1%_2  [R0201]  146.25 102.31 180 bottom
PR8002  1K_1%_2  [R0201]  197.33 77.54 180 bottom
PR8006  10K_1%_2  [R0201]  142.44 99.01 0 bottom
PR8008  1K_1%_2  [R0201]  199.69 73.94 270 bottom
PR8009  100K_1%_2  [R0201]  151.21 100.64 90 top
PR8011  100K_1%_2  [R0201]  142.44 98.24 180 bottom
PR8013  100K_1%_2  [R0201]  194.21 70.89 90 bottom
PR8014  549K_1%_2  [R0201]  157.3 105.13 90 top
PR8015  76.8K_1%_2  [R0201]  157.17 105.99 0 top
PR8016  100K_1%_2  [R0201]  175.33 92.33 90 bottom
PR8017  100K_1%_2  [R0201]  175.36 82.24 0 bottom
PR8018  470K_5%_2  [R0201]  173.61 101.29 0 bottom
PR8019  1M_1%_2  [R0201]  161.57 104.11 90 top
PR8020  33K_1%_2  [R0201]  162.35 104.11 90 top
PR8021  220K_5%_2  [R0201]  161.69 105.51 0 top
PR8022  100K_1%_2  [R0201]  163.07 104.11 90 top
PR8023  100K_1%_2  [R0201]  179.14 90.88 270 bottom
PR8024  100K_1%_2  [R0201]  172.01 84.5 0 bottom
PR8025  470K_5%_2  [R0201]  178.43 90.88 90 bottom
PR8026  470K_5%_2  [R0201]  175.36 83 0 bottom
PR8027  2.2_5%_8  [R0805]  156.92 100.91 0 bottom
PR8028  *Short_0201  [S0201]  169.9 103.58 0 bottom
PR8029  *Short_0201  [S0201]  169.72 101.04 0 bottom
PR8100  115K_1%_2  [R0201]  36.5 8.63 180 bottom
PR8101  76.8K_1%_2  [R0201]  37.49 8.63 0 bottom
PR8102  51.1K_1%_2  [R0201]  35.2 10.95 0 bottom
PR8103  41.2K_1%_2  [R0201]  199.97 45.51 270 top
PR8104  28K_1%_2  [R0201]  209.27 10.21 270 bottom
PR8105  3.3K_1%_2  [R0201]  107.57 13.46 0 top
PR8106  57.6K_1%_2  [R0201]  35.68 13.15 0 bottom
PR8107  *3.3K_1%_2  [R0201]  122.02 18.06 0 bottom
PR8108  31.6K_1%_2  [R0201]  42.68 11.56 180 bottom
PR8109  1K_1%_2  [R0201]  181.62 57.25 180 bottom
PR8110  3.3K_1%_2  [R0201]  179.42 56.97 180 bottom
PR8111  10K_1%_2  [R0201]  40.69 11.55 0 bottom
PR8112  10K_1%_2  [R0201]  36.7 11.68 180 bottom
PR8113  18.7K_1%_2  [R0201]  37.69 11.53 180 bottom
PR8114  22.6K_1%_2  [R0201]  35.48 9.24 180 bottom
PR8115  1M_1%_2  [R0201]  41.68 11.55 0 bottom
PR8116  1M_1%_2  [R0201]  36.7 12.39 180 bottom
PR8117  20K_1%_2  [R0201]  43.46 10.56 180 bottom
PR8118  20K_1%_2  [R0201]  35.2 11.96 0 bottom
PR8119  100K_1%_4  [R0402]  172.06 18.36 90 top
PR8120  68.1K_1%_4  [R0402]  170.53 18.62 180 top
PR8121  10K_5%_4  [R0402]  189.82 14.4 270 bottom
PR8122  *100K_1%_4  [R0402]  178.41 15.69 180 top
PR8123  *Short_0201  [S0201]  177.42 12.77 0 top
PR8124  10K_5%_4  [R0402]  185.57 11.71 90 top
PR8125  10_1%_4  [R0402]  185.39 12.39 0 bottom
PR8126  100K_1%_4  [R0402]  185.39 11.43 0 bottom
PR8127  *10K_1%_4  [R0402]  165.43 70.25 270 top
PR8200  0.01_1%_12  [R1206]  177.77 86 270 bottom
PR8201  *Short_0201  [S0201]  177.77 85.37 270 bottom
PR8202  *Short_0201  [S0201]  177.77 86.64 90 bottom
PR8203  100K_1%_2  [R0201]  52.42 13.26 90 top
PR8204  470K_5%_2  [R0201]  55.04 16.94 270 top
PR8205  100_1%_4  [R0402]  59.23 10.54 90 top
PR8206  100_1%_4  [R0402]  60.2 10.54 90 top
PR8207  100K_1%_2  [R0201]  67.79 15.49 90 bottom
PR8208  470K_5%_2  [R0201]  51.71 13.26 270 top
PR8209  *Short_0402  [S0402]  60.07 9.14 180 top
PR8210  4.02K_1%_4  [R0402]  58.27 12.34 270 top
PR8211  10_5%_8  [R0805]  62.56 11.24 0 top
PR8212  1_5%_6  [R0603]  62.99 4.89 0 top
PR8213  249K_1%_2  [R0201]  56.34 12.14 270 top
PR8214  *Short_0402  [S0402]  169.72 102.31 90 bottom
PR8215  0.005_1%_12  [R1206]  73.1 12.7 270 bottom
PR8216  *Short_0402  [S0402]  169.93 104.82 90 bottom
PR8217  53.6K_1%_2  [R0201]  56.36 10.57 180 top
PR8218  *2.2_5%_6  [R0603]  65.53 6.3 270 top
PR8219  27K_1%_2  [R0201]  53.87 8.15 90 bottom
PR8220  47K_1%_2  [R0201]  53.13 8.15 90 bottom
PR8221  *Short_0201  [S0201]  73.1 12.01 270 bottom
PR8222  *Short_0201  [S0201]  73.1 13.41 90 bottom
PR8223  *Short_0201  [S0201]  54.25 6.55 90 top
PR8224  *Short_0201  [S0201]  52.45 7.29 90 top
PR8225  *Short_0201  [S0201]  53.54 7.74 0 top
PR8226  *0_5%_2  [R0201]  54.38 2.54 270 top
PR8227  10_1%_6  [R0603]  71.09 3.27 180 top
PR8228  *Short_0201  [S0201]  55.24 2.66 0 top
PR8229  *Short_0603  [S0603]  69.04 7.31 270 top
PR8230  22K_1%_2  [R0201]  57.35 10.49 0 top
PR8231  *Short_0603  [S0603]  70.56 7.31 270 top
PR8232  2M_1%_2  [R0201]  56.72 9.45 180 top
PR8233  *Short_0201  [S0201]  55.45 12.14 270 top
PR8234  *Short_0201  [S0201]  54.43 12.14 270 top
PR8235  47K_1%_2  [R0201]  57.3 3.96 90 bottom
PR8236  *0_5%_2  [R0201]  53.19 8.61 90 top
PR8237  *0_5%_2  [R0201]  53.95 8.61 90 top
PR8238  10K_1%_2  [R0201]  58.16 4.16 180 bottom
PR8239  47K_1%_2  [R0201]  53.16 4.72 270 top
PR8240  249K_1%_2  [R0201]  51.71 7.29 270 top
PR8241  1M_1%_2  [R0201]  54.05 5.28 270 top
PR8242  *Short_0201  [S0201]  52.4 4.72 270 top
PR8243  28K_1%_2  [R0201]  50.92 7.29 270 top
PR8244  402_1%_2  [R0201]  50.38 6.14 270 top
PR8245  *Short_0201  [S0201]  58.65 14.25 270 top
PR8400  49.9K_1%_2  [R0201]  174.41 86.21 180 top
PR8401  301K_1%_2  [R0201]  173.14 86.17 0 top
PR8402  100K_1%_2  [R0201]  189.43 49.38 0 bottom
PR8403  49.9K_1%_2  [R0201]  173.3 84.66 270 top
PR8404  9.09K_1%_2  [R0201]  191.36 53.67 0 bottom
PR8405  3.32K_1%_2  [R0201]  190.29 53.67 0 bottom
PR8406  1.87K_1%_2  [R0201]  190.42 49.38 180 bottom
PR8407  1.87K_1%_2  [R0201]  191.41 49.38 180 bottom
PR8408  9.09K_1%_2  [R0201]  189.25 53.85 90 bottom
PR8409  100K_1%_2  [R0201]  189.25 52.7 270 bottom
PR8410  *Short_0201  [S0201]  157.38 60.68 180 bottom
PR8411  *Short_0201  [S0201]  155.01 64.34 0 bottom
PR8412  100K_1%_2  [R0201]  53.21 3.73 90 top
PR8413  *549K_1%_4  [R0402]  49.73 9.64 180 top
PR8414  1.21K_1%_2  [R0201]  90.27 9.83 180 top
PR8415  *76.8K_1%_4  [R0402]  49.37 6.5 270 top
PR8416  *220K_1%_4  [R0402]  44.67 6.35 270 top
PR8417  *100K_1%_4  [R0402]  43.24 6.66 180 top
PR8418  100_1%_4  [R0402]  81.24 15.8 270 bottom
PR8419  100_1%_4  [R0402]  84.14 15.8 270 bottom
PR8420  *100_1%_4  [R0402]  87.68 15.35 0 bottom
PR8421  *Short_0201  [S0201]  72.72 11.94 180 top
PR8422  *Short_0201  [S0201]  73.18 8.71 180 top
PR8600  *Short_0201  [S0201]  140.65 17.54 0 bottom
PR8601  *Short_1206  [S1206]  151.29 13.18 180 top
PR8602  1_5%_6  [R0603]  144.04 12.27 90 bottom
PR8605  *2.2_5%_6  [R0603]  144.84 15.19 0 top
PR8606  *Short_0201  [S0201]  139.22 12.32 0 bottom
PR8607  *Short_0201  [S0201]  145.74 16.61 270 top
PR8608  *0_5%_2  [R0201]  141.15 12.85 270 bottom
PR8609  *Short_0402  [S0402]  142.83 11.4 270 bottom
PR8610  *Short_1206  [S1206]  175.11 9.85 180 bottom
PR8612  1_5%_6  [R0603]  167.43 17.6 180 bottom
PR8613  100K_1%_2  [R0201]  170.64 10.21 270 bottom
PR8614  *2.2_5%_6  [R0603]  172.11 16.53 0 top
PR8615  *Short_0201  [S0201]  172.29 10.61 180 bottom
PR8616  *150K_1%_2  [R0201]  169.92 10.21 270 bottom
PR8617  *Short_0201  [S0201]  169.44 11.33 90 bottom
PR8618  1K_1%_4  [R0402]  168.86 10.84 180 top
PR8619  100K_1%_2  [R0201]  167.79 9.95 90 bottom
PR8620  137K_1%_4  [R0402]  170.28 12.57 180 top
PR8621  100K_1%_2  [R0201]  169.21 9.95 270 bottom
PR8622  18.2K_1%_4  [R0402]  168.53 12.52 180 top
PR8623  *0_5%_2  [R0201]  140.59 14.35 0 bottom
PR8700  *Short_0201  [S0201]  107.57 12.75 0 top
PR8701  *Short_0201  [S0201]  107.54 10.28 180 bottom
PR8702  105K_1%_2  [R0201]  104.16 14.3 0 top
PR8703  *Short_0201  [S0201]  107.57 11.31 180 top
PR8704  499K_1%_2  [R0201]  107.57 12.04 0 top
PR8705  2.2_5%_6  [R0603]  100.1 12.14 180 top
PR8706  *Short_1206  [S1206]  113.43 17.4 180 bottom
PR8707  100_5%_4  [R0402]  105.64 8 270 top
PR8708  *2.2_5%_6  [R0603]  100.4 14.53 180 top
PR8709  *Short_0603  [S0603]  102.33 9.07 0 bottom
PR8710  *Short_0201  [S0201]  103.84 8.36 270 top
PR8711  *Short_0201  [S0201]  110.59 12.27 0 bottom
PR8712  *Short_0201  [S0201]  105.15 14.3 180 top
PR8713  *0_5%_2  [R0201]  106.6 8.51 90 top
PR8714  7.87K_1%_2  [R0201]  106.14 9.36 180 top
PR8715  10K_1%_2  [R0201]  107 9.55 270 top
PR8716  *Short_0201  [S0201]  177.95 17.4 90 bottom
PR8717  *Short_0603  [S0603]  184.66 27.25 180 top
PR8718  22_5%_8  [R0805]  117.45 15.62 0 top
PR8719  *Short_0603  [S0603]  183.34 13.69 270 bottom
PR8720  220K_5%_2  [R0201]  161.97 13.61 180 top
PR8721  *Short_0201  [S0201]  186.99 17.37 0 bottom
PR8722  100_1%_4  [R0402]  170.08 49.22 90 top
PR8723  32.4K_1%_2  [R0201]  189.25 17.25 90 bottom
PR8724  150K_1%_2  [R0201]  173.07 48.61 0 top
PR8725  10K_1%_2  [R0201]  189.25 18.23 270 bottom
PR8800  100_1%_2  [R0201]  81.21 110.92 0 top
PR8801  *110_1%_2  [R0201]  80.39 109.34 270 top
PR8802  45.3_1%_2  [R0201]  79.7 107.77 0 top
PR8803  *75_1%_2  [R0201]  79.4 106.53 0 top
PR8804  2.2_5%_6  [R0603]  82.13 111.05 90 bottom
PR8805  2.2_5%_6  [R0603]  81.77 107.28 270 bottom
PR8806  100K_1%_2  [R0201]  89.45 106.04 180 top
PR8807  100K_1%_2  [R0201]  91.82 103.27 270 top
PR8808  3.65K_1%_6  [R0603]  90.14 103.31 0 top
PR8809  63.4K_1%_2  [R0201]  83.53 108.74 270 bottom
PR8810  10K_NTC_4_1%  [R0402]  92.3 100.61 270 bottom
PR8811  150K_1%_2  [R0201]  84.38 108.77 270 bottom
PR8812  100K_1%_2  [R0201]  90.28 100.78 0 top
PR8813  100K_1%_2  [R0201]  85.23 108.77 270 bottom
PR8814  11K_1%_2  [R0201]  90.02 102.54 90 bottom
PR8815  100K_1%_2  [R0201]  91.82 101.55 90 top
PR8816  3.65K_1%_6  [R0603]  90.14 101.87 0 top
PR8817  4.7K_1%_2  [R0201]  90.17 103.4 0 bottom
PR8818  2K_1%_4  [R0402]  82.46 102.59 90 top
PR8819  1_1%_2  [R0201]  89.26 100.78 180 top
PR8820  732_1%_2  [R0201]  87.76 102.69 0 top
PR8821  1_1%_2  [R0201]  90.94 105.99 0 top
PR8822  4.02K_1%_2  [R0201]  85.02 105.6 90 bottom
PR8823  3.48K_1%_4  [R0402]  88.27 101.29 270 top
PR8824  10K_1%_2  [R0201]  80.85 105.47 180 top
PR8825  *Short_0201  [S0201]  80.86 106.19 0 top
PR8826  *Short_0201  [S0201]  89.38 109.17 0 top
PR8827  *Short_0201  [S0201]  80.85 104.73 0 top
PR8828  *4.7_5%_4  [R0402]  84.38 102.59 90 top
PR8829  *Short_0201  [S0201]  80.86 106.9 0 top
PR8830  499_1%_4  [R0402]  86.3 102.59 270 top
PR8831  *Short_0201  [S0201]  81.21 110.2 0 top
PR8832  100_1%_2  [R0201]  106.58 68.71 180 top
PR8833  *Short_0201  [S0201]  80.19 108.48 0 top
PR8834  3.01K_1%_2  [R0201]  85.34 102.59 90 top
PR8835  *Short_0201  [S0201]  80.69 107.77 0 top
PR8836  *0_5%_2  [R0201]  80.85 103.94 180 top
PR8837  100_1%_2  [R0201]  105.59 71.23 180 top
PR8838  10K_1%_2  [R0201]  84.2 105.08 90 bottom
PR8839  8.06K_1%_2  [R0201]  81.38 102.46 180 top
PR8840  102K_1%_2  [R0201]  83.74 103.18 270 bottom
PR8841  470K_NTC_4_5%  [R0402]  91.39 103.66 270 bottom
PR8842  27K_1%_2  [R0201]  80.39 102.46 180 top
PR8843  *Short_0201  [S0201]  106.58 69.42 180 top
PR8844  *Short_0201  [S0201]  105.59 70.5 180 top
PR8845  *0_5%_2  [R0201]  88.14 104.85 270 bottom
PR8846  *0_5%_2  [R0201]  88.87 104.85 270 bottom
PR8900  2.2_5%_6  [R0603]  90.19 109.19 270 bottom
PR8901  1_5%_6  [R0603]  94.52 111.26 90 bottom
PR8902  *Short_0201  [S0201]  91.8 108.64 0 bottom
PR8903  *Short_0201  [S0201]  92.43 109.65 270 bottom
PR8904  *2.2_5%_6  [R0603]  94.89 102.13 0 top
PR8905  *Short_0201  [S0201]  96.03 99.46 180 bottom
PR8906  *Short_0201  [S0201]  99.46 99.39 0 bottom
PR8907  2.2_5%_6  [R0603]  103.55 110.94 90 bottom
PR8908  1_5%_6  [R0603]  105.51 111.67 90 bottom
PR8909  *Short_0201  [S0201]  103.42 108.69 0 bottom
PR8910  *Short_0201  [S0201]  104.43 109.25 0 bottom
PR8911  *2.2_5%_6  [R0603]  104.87 102.21 0 top
PR8912  *Short_0201  [S0201]  108.95 99.49 0 bottom
PR8913  *Short_0201  [S0201]  105.35 99.49 180 bottom
PR8914  *Short_1206  [S1206]  90.78 111.33 0 top
PR9100  100K_1%_2  [R0201]  122.88 105.36 0 top
PR9101  100K_1%_2  [R0201]  122.88 106.12 0 top
PR9102  *100K_1%_2  [R0201]  121.23 105.41 0 top
PR9103  *100K_1%_2  [R0201]  121.23 106.17 0 top
PR9104  5.1_1%_6  [R0603]  111.1 109.19 180 bottom
PR9105  *Short_0201  [S0201]  118.44 107.9 180 bottom
PR9106  *Short_0201  [S0201]  118.44 107.13 180 bottom
PR9107  1_5%_6  [R0603]  112.01 102.4 180 bottom
PR9108  10K_1%_2  [R0201]  117.65 106.23 90 top
PR9109  *Short_0201  [S0201]  118.54 106.23 270 top
PR9110  *2.2_5%_6  [R0603]  117.07 103.71 270 top
PR9111  *200K_1%_2  [R0201]  113.27 105.79 0 top
PR9112  1_5%_6  [R0603]  118.86 103.83 0 bottom
PR9114  *Short_0201  [S0201]  128.45 105.53 90 bottom
PR9115  100_1%_2  [R0201]  113.71 90.45 180 bottom
PR9116  *200K_1%_2  [R0201]  113.27 106.5 0 top
PR9117  150K_1%_2  [R0201]  118.44 106.25 0 bottom
PR9118  100_1%_2  [R0201]  112.65 90.47 0 bottom
PR9119  1M_5%_2  [R0201]  128.74 103.29 180 bottom
PR9120  22_5%_8  [R0805]  122.88 103.71 180 bottom
PR9121  *Short_0201  [S0201]  127.71 105.53 90 bottom
PR9122  2M_1%_2  [R0201]  128.57 104.16 90 bottom
PR9123  *Short_1206  [S1206]  111.05 110.13 270 top
PR9124  *Short_0201  [S0201]  113.38 89.56 90 bottom
PR9125  *Short_0201  [S0201]  112.62 89.56 90 bottom
PR9203  1_5%_6  [R0603]  124.53 12.93 270 bottom
PR9204  *Short_0402  [S0402]  121.88 11.45 180 bottom
PR9205  *Short_1206  [S1206]  131.9 14.37 180 top
PR9206  *Short_0201  [S0201]  122.91 17.83 90 bottom
PR9207  *2.2_6  [R0603]  127.4 14.44 0 top
PR9208  *Short_0201  [S0201]  130.78 17.93 0 bottom
PR9209  *0_5%_2  [R0201]  120.56 12.29 0 bottom
PR9210  *1M_1%_2  [R0201]  120.72 13.1 180 bottom
PR9212  40.2K_1%_2  [R0201]  122.15 14.3 0 top
PR9213  20K_1%_2  [R0201]  121.72 13.11 180 bottom
PR9214  10K_1%_2  [R0201]  123.89 16.48 180 top
PR9500  *Short_0603  [S0603]  16.79 13.49 270 top
PR9501  *Short_0805  [S0805]  29.53 11.77 90 top
PR9502  *Short_0805  [S0805]  159.64 11.68 0 top
PR9503  *Short_0603  [S0603]  153.45 7.57 270 top
PR9504  *Short_0201  [S0201]  158.09 15.26 180 top
PR9505  *Short_0201  [S0201]  155.47 16.18 180 top
PR9507  *Short_0201  [S0201]  26.87 7.28 270 top
PR9509  *Short_0603  [S0603]  178.03 72.16 180 top
PR9510  *0.01_1%_6  [R0603]  171.75 70.97 180 top
PR9513  *0_5%_2  [R0201]  173.3 63.07 180 top
PR9514  20K_1%_2  [R0201]  177.82 65.12 180 top
PR9518  *Short_0201  [S0201]  156.46 16.18 180 top
PR9520  *Short_0201  [S0201]  159.08 15.49 0 top
PR9522  *Short_0201  [S0201]  173.3 62.33 0 top
PR9600  *Short_0201  [S0201]  142.57 90.75 270 top
PR9601  *0_5%_2  [R0201]  141.83 90.75 270 top
PR9603  *100K_2  [R0201]  144.24 96.77 270 bottom
PR9606  *100K_2  [R0201]  143.91 92.89 270 top
PR9611  *100K_2  [R0201]  150.32 101.67 180 top
PR9612  *0_5%_2  [R0201]  139.6 97.13 180 top
PR9613  *Short_0201  [S0201]  139.72 98.5 90 top
PR9800  10K_1%_2  [R0201]  33.48 106.35 90 top
PR9801  *Short_0201  [S0201]  33.48 107.34 270 top
PR9802  *Short_0201  [S0201]  32.76 107.34 270 top
PR9803  10K_1%_2  [R0201]  32.76 106.35 90 top
PR9804  *Short_0201  [S0201]  31.77 105.38 0 top
PR9805  *0_5%_2  [R0201]  31.77 106.09 0 top
PR9806  3M_5%_2  [R0201]  34.82 100.15 270 top
PR9807  200K_1%_2  [R0201]  34.11 100.15 90 top
PR9808  10K_1%_2  [R0201]  35.15 106.63 90 bottom
PR9809  100_1%_2  [R0201]  30.33 100.18 270 top
PR9810  *Short_0201  [S0201]  35.15 106.63 270 top
PR9811  *Short_0201  [S0201]  31.72 102.18 180 top
PR9812  12K_1%_2  [R0201]  34.44 106.63 90 top
PR9813  *Short_0201  [S0201]  31.75 101.47 180 top
PR9814  *Short_0201  [S0201]  38.33 105.15 180 top
PR9815  100_1%_2  [R0201]  31.04 100.18 270 top
